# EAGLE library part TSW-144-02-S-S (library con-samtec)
THROUGH-HOLE .025" SQ POST HEADER Source: Samtec TSW.pdf
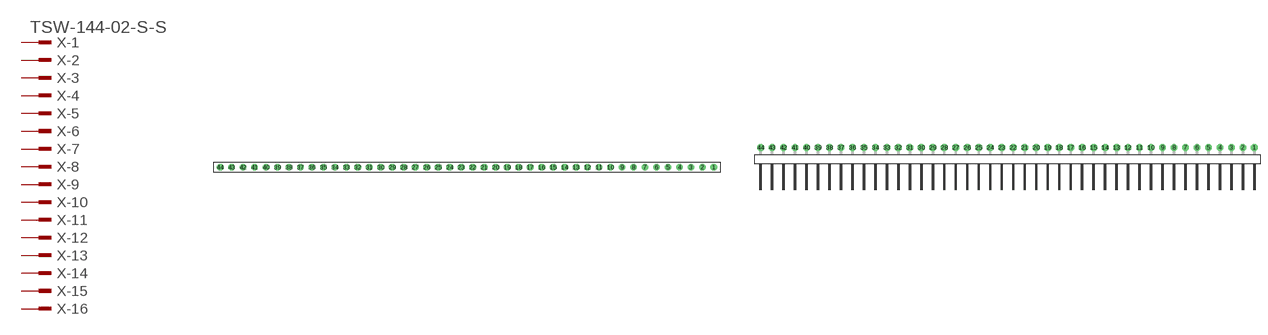
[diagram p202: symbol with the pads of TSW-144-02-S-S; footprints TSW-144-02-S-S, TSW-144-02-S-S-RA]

Designator prefix X; gates -1=MPINV -2=MPIN -3=MPIN -4=MPIN -5=MPIN -6=MPIN -7=MPIN -8=MPIN -9=MPIN -10=MPIN -11=MPIN -12=MPIN -13=MPIN -14=MPIN -15=MPIN -16=MPIN -17=MPIN -18=MPIN -19=MPIN -20=MPIN -21=MPIN -22=MPIN -23=MPIN -24=MPIN -25=MPIN -26=MPIN -27=MPIN -28=MPIN -29=MPIN -30=MPIN -31=MPIN -32=MPIN -33=MPIN -34=MPIN -35=MPIN -36=MPIN -37=MPIN -38=MPIN -39=MPIN -40=MPIN -41=MPIN -42=MPIN -43=MPIN -44=MPIN

## TSW-144-02-S-S (OC_FARNELL: unknown; OC_NEWARK: unknown)  [TSW-144-02-S-S]
1  -1:1  pas
2  -2:1  pas
3  -3:1  pas
4  -4:1  pas
5  -5:1  pas
6  -6:1  pas
7  -7:1  pas
8  -8:1  pas
9  -9:1  pas
10  -10:1  pas
11  -11:1  pas
12  -12:1  pas
13  -13:1  pas
14  -14:1  pas
15  -15:1  pas
16  -16:1  pas
17  -17:1  pas
18  -18:1  pas
19  -19:1  pas
20  -20:1  pas
21  -21:1  pas
22  -22:1  pas
23  -23:1  pas
24  -24:1  pas
25  -25:1  pas
26  -26:1  pas
27  -27:1  pas
28  -28:1  pas
29  -29:1  pas
30  -30:1  pas
31  -31:1  pas
32  -32:1  pas
33  -33:1  pas
34  -34:1  pas
35  -35:1  pas
36  -36:1  pas
37  -37:1  pas
38  -38:1  pas
39  -39:1  pas
40  -40:1  pas
41  -41:1  pas
42  -42:1  pas
43  -43:1  pas
44  -44:1  pas

## TSW-144-02-S-S-RA (OC_FARNELL: unknown; OC_NEWARK: unknown)  [TSW-144-02-S-S-RA]
Pads as for TSW-144-02-S-S

## Footprint TSW-144-02-S-S (pad centres in mm)
THROUGH-HOLE .025" SQ POST HEADER Source: Samtec TSW.pdf
drill 1 pad 1.5 octagon: 1 54.61,0; 2 52.07,0; 3 49.53,0; 4 46.99,0; 5 44.45,0; 6 41.91,0; 7 39.37,0; 8 36.83,0; 9 34.29,0; 10 31.75,0; 11 29.21,0; 12 26.67,0; 13 24.13,0; 14 21.59,0; 15 19.05,0; 16 16.51,0; 17 13.97,0; 18 11.43,0; 19 8.89,0; 20 6.35,0; 21 3.81,0; 22 1.27,0; 23 -1.27,0; 24 -3.81,0; 25 -6.35,0; 26 -8.89,0; 27 -11.43,0; 28 -13.97,0; 29 -16.51,0; 30 -19.05,0; 31 -21.59,0; 32 -24.13,0; 33 -26.67,0; 34 -29.21,0; 35 -31.75,0; 36 -34.29,0; 37 -36.83,0; 38 -39.37,0; 39 -41.91,0; 40 -44.45,0; 41 -46.99,0; 42 -49.53,0; 43 -52.07,0; 44 -54.61,0

## Footprint TSW-144-02-S-S-RA (pad centres in mm)
THROUGH-HOLE .025" SQ POST HEADER Source: Samtec TSW.pdf
drill 1 pad 1.5 octagon: 1 54.61,1.524; 2 52.07,1.524; 3 49.53,1.524; 4 46.99,1.524; 5 44.45,1.524; 6 41.91,1.524; 7 39.37,1.524; 8 36.83,1.524; 9 34.29,1.524; 10 31.75,1.524; 11 29.21,1.524; 12 26.67,1.524; 13 24.13,1.524; 14 21.59,1.524; 15 19.05,1.524; 16 16.51,1.524; 17 13.97,1.524; 18 11.43,1.524; 19 8.89,1.524; 20 6.35,1.524; 21 3.81,1.524; 22 1.27,1.524; 23 -1.27,1.524; 24 -3.81,1.524; 25 -6.35,1.524; 26 -8.89,1.524; 27 -11.43,1.524; 28 -13.97,1.524; 29 -16.51,1.524; 30 -19.05,1.524; 31 -21.59,1.524; 32 -24.13,1.524; 33 -26.67,1.524; 34 -29.21,1.524; 35 -31.75,1.524; 36 -34.29,1.524; 37 -36.83,1.524; 38 -39.37,1.524; 39 -41.91,1.524; 40 -44.45,1.524; 41 -46.99,1.524; 42 -49.53,1.524; 43 -52.07,1.524; 44 -54.61,1.524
